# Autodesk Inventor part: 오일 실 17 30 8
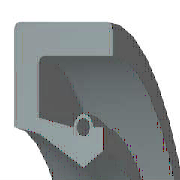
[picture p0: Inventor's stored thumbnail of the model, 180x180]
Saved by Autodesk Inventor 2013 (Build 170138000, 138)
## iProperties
IsCustomPart: 1
Created: 2012-02
Part Number: 오일 실 17 30 8
Material: 고무
Description: 오일-실
Document SubType Name: Modeling
Standard: KS B 2804
Designer: test
Standards Organization: KS
Language: ko-KR
Size Designation: S - 17 32 8
Categories: <MemberInstance><Categories><Category DisplayName="샤프트 부품" InternalName="7f7aeb1f-a693-4053-b835-cee3144e0d98" Mnemonic="SHFT"><Category DisplayName="실링" Intern
Density: 0.93 g/cm^3
Mass: 1.6913 g
Surface Area: 28.0102 cm^2
Volume: 1.81861 cm^3
Author: test
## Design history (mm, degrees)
revolve "본체" stored, may be unused: angle "d17" = 90 deg
revolve "스프링1" stored, may be unused: angle "d18" = 90 deg
body "Solid1"
sketch "스케치1"
  geometry: L1 (0, 15)-(8, 15); L2 (8, 15)-(8, 13.75); L3 (8, 13.75)-(1.75, 13.75); L4 (0, 15)-(0, 10.6); L5 (0, 10.6)-(1.75, 10.25); L6 (1.75, 10.25)-(4.9, 8.5); L7 (4.9, 8.5)-(0, 8.5); L8 (6.3, 9.375)-(6.3, 10.6); L9 (0, 0)-(9.586, 0) reference; L10 (4.9, 8.5)-(6.3, 9.375); L11 (0, 19.2)-(0, -3.2) reference; L12 (-1.917, 0)-(11.503, 0) reference; L13 (4.2, 10.6)-(1.75, 11.09); L14 (1.75, 11.09)-(1.75, 13.75); L15 (6.3, 10.6)-(5.6, 10.6); C1 r 0.455 at (4.9, 10.6); A1 r 0.7 centre (4.9, 10.6) between (5.6, 10.6) and (4.2, 10.6)
  constraints: 26 end point, 5 horizontal alignment, 4 perpendicular, 2 centre point, 2 collinear, 2 horizontal, 2 parallel, 2 point on circle, 2 point on line, 2 vertical alignment, 1 coincident
  dimensions: "d0" = 30 diameter of L1 L9 (= SD2); "d1" = 18.75 diameter of L8.start L9 (= ABDM); "d2" = 1.25 distance of L1.end L2.end (computed from SD); "d3" = 0.91 diameter of C1 (= SPDI); "d4" = 1.4 diameter of A1 (= SPDA); "d5" = 17 diameter of L6.end L9 (= NND); "d6" = 20.5 diameter of L5.end L9 (= TKDM); "d7" = 21.2 diameter of L4.end L9 (= HLDM); "d8" = 4.9 distance from line of C1.centre L4 (= SPDST); "d9" = 6.3 distance between parallel lines of L8 L4 (= SDI); "d10" = 8 distance between parallel lines of L2 L4 (= SWDT); "d12" = 1.75 distance between parallel lines of L14 L4 (= SD)
fillet "모깎기1" dims "d11" = 0.3 (= RR)
other parameters: "SD2" = 30 [user parameter; used in 1 equation term], "SWDT" = 8 [user parameter; used in 1 equation term], "RR" = 0.3 [user parameter; used in 1 equation term], "SD" = 1.75 [user parameter; used in 2 equation terms], "NND" = 17 [user parameter; used in 1 equation term], "SPDA" = 1.4 [user parameter; used in 1 equation term], "SPDI" = 0.91 [user parameter; used in 1 equation term], "TKDM" = 20.5 [user parameter; used in 1 equation term], "HLDM" = 21.2 [user parameter; used in 1 equation term], "ABDM" = 18.75 [user parameter; used in 1 equation term], "SDI" = 6.3 [user parameter; used in 1 equation term], "SPDST" = 4.9 [user parameter; used in 1 equation term], "d13" = 0, "d14" = 0, "d15" = 0, "LAB" = 0.35 [user parameter]
